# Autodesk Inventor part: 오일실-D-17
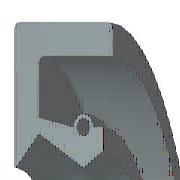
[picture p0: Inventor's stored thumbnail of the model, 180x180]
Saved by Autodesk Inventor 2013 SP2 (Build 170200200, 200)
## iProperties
IsCustomPart: 0
Company: 한국ATC센터
Created: 2014-12
Part Number: 오일실-D-17
Material: 고무
Description: 오일-실
Document SubType Name: Modeling
Standard: KS B 2804
Designer: KYOUNG IL JANG
Standards Organization: KS
Language: ko-KR
Size Designation: D - 17 30 8
Categories: <MemberInstance><Categories><Category DisplayName="샤프트 부품" InternalName="7f7aeb1f-a693-4053-b835-cee3144e0d98" Mnemonic="SHFT"><Category DisplayName="실링" Intern
Density: 0.93 g/cm^3
Mass: 2.05797 g
Surface Area: 29.3036 cm^2
Volume: 2.21288 cm^3
Author: KYOUNG IL JANG
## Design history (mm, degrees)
revolve "본체" stored, may be unused: angle "d17" = 90 deg
revolve "스프링1" stored, may be unused: angle "d18" = 90 deg
body "Solid1"
sketch "스케치1"
  geometry: L1 (0, 15)-(8, 15); L2 (8, 13.25)-(1.75, 13.25); L3 (1.75, 10.25)-(4.9, 8.5); L4 (4.9, 8.5)-(0, 8.5); L5 (0, 0)-(9.586, 0) reference; L6 (4.9, 8.5)-(6.3, 9.375); L7 (0, 18)-(0, -3) reference; L8 (-1.941, 0)-(11.507, 0) reference; L9 (4.2, 10.6)-(1.75, 11.21); L10 (1.75, 11.21)-(1.75, 13.25); L11 (0, 15)-(0, 8.588); L12 (4.9, 8.5)-(0, 8.5); L13 (1.75, 10.25)-(0.152, 8.528); L14 (8, 15)-(8, 13.25); L15 (5.6, 10.6)-(6.3, 10.6); L16 (6.3, 10.6)-(6.3, 9.375); C1 r 0.455 at (4.9, 10.6); A1 r 0.7 centre (4.9, 10.6) between (5.6, 10.6) and (4.2, 10.6); A2 r 0.088 centre (0.088, 8.588) between (0, 8.588) and (0.152, 8.528); 1 further point
  constraints: 28 end point, 5 horizontal alignment, 5 point on line, 4 point on circle, 4 vertical alignment, 3 centre point, 3 tangent, 2 collinear, 2 horizontal, 2 perpendicular, 1 coincident, 1 parallel
  dimensions: "d0" = 30 diameter of L1 L5 (= SD2); "d1" = 1.75 distance of L1.end L2.start (= SD); "d2" = 0.91 diameter of C1 (= SPDI); "d3" = 1.4 diameter of A1 (= SPDA); "d4" = 17 diameter of L3.end L5 (= NND); "d5" = 20.5 diameter of L3.start L5 (= TKDM); "d7" = 22.42 diameter of L9.end L5 (= TKDM + 0.24 x SWDT); "d8" = 1.75 distance between parallel lines of L11 L10 (= SD); "d9" = 4.9 distance from line of L11 C1.centre (= SPDST); "d10" = 21.2 diameter of C1.centre L5 (= HLDM); "d11" = 0.0875 radius of A2 (= 0.25 x LAB); "d12" = 6.3 distance between parallel lines of L11 L16 (= SDI); "d13" = 18.75 diameter of L6.end L5 (= ABDM); "d14" = 8 distance from line of L11 L1.end (= SWDT)
fillet "모깎기1" dims "d6" = 0.3 (= RR)
other parameters: "SD2" = 30 [user parameter; used in 1 equation term], "SWDT" = 8 [user parameter; used in 2 equation terms], "RR" = 0.3 [user parameter; used in 1 equation term], "SD" = 1.75 [user parameter; used in 2 equation terms], "NND" = 17 [user parameter; used in 1 equation term], "SPDA" = 1.4 [user parameter; used in 1 equation term], "SPDI" = 0.91 [user parameter; used in 1 equation term], "TKDM" = 20.5 [user parameter; used in 2 equation terms], "HLDM" = 21.2 [user parameter; used in 1 equation term], "ABDM" = 18.75 [user parameter; used in 1 equation term], "SDI" = 6.3 [user parameter; used in 1 equation term], "SPDST" = 4.9 [user parameter; used in 1 equation term], "LAB" = 0.35 [user parameter; used in 1 equation term], "d15" = 0, "d16" = 0, "d19" = 0
